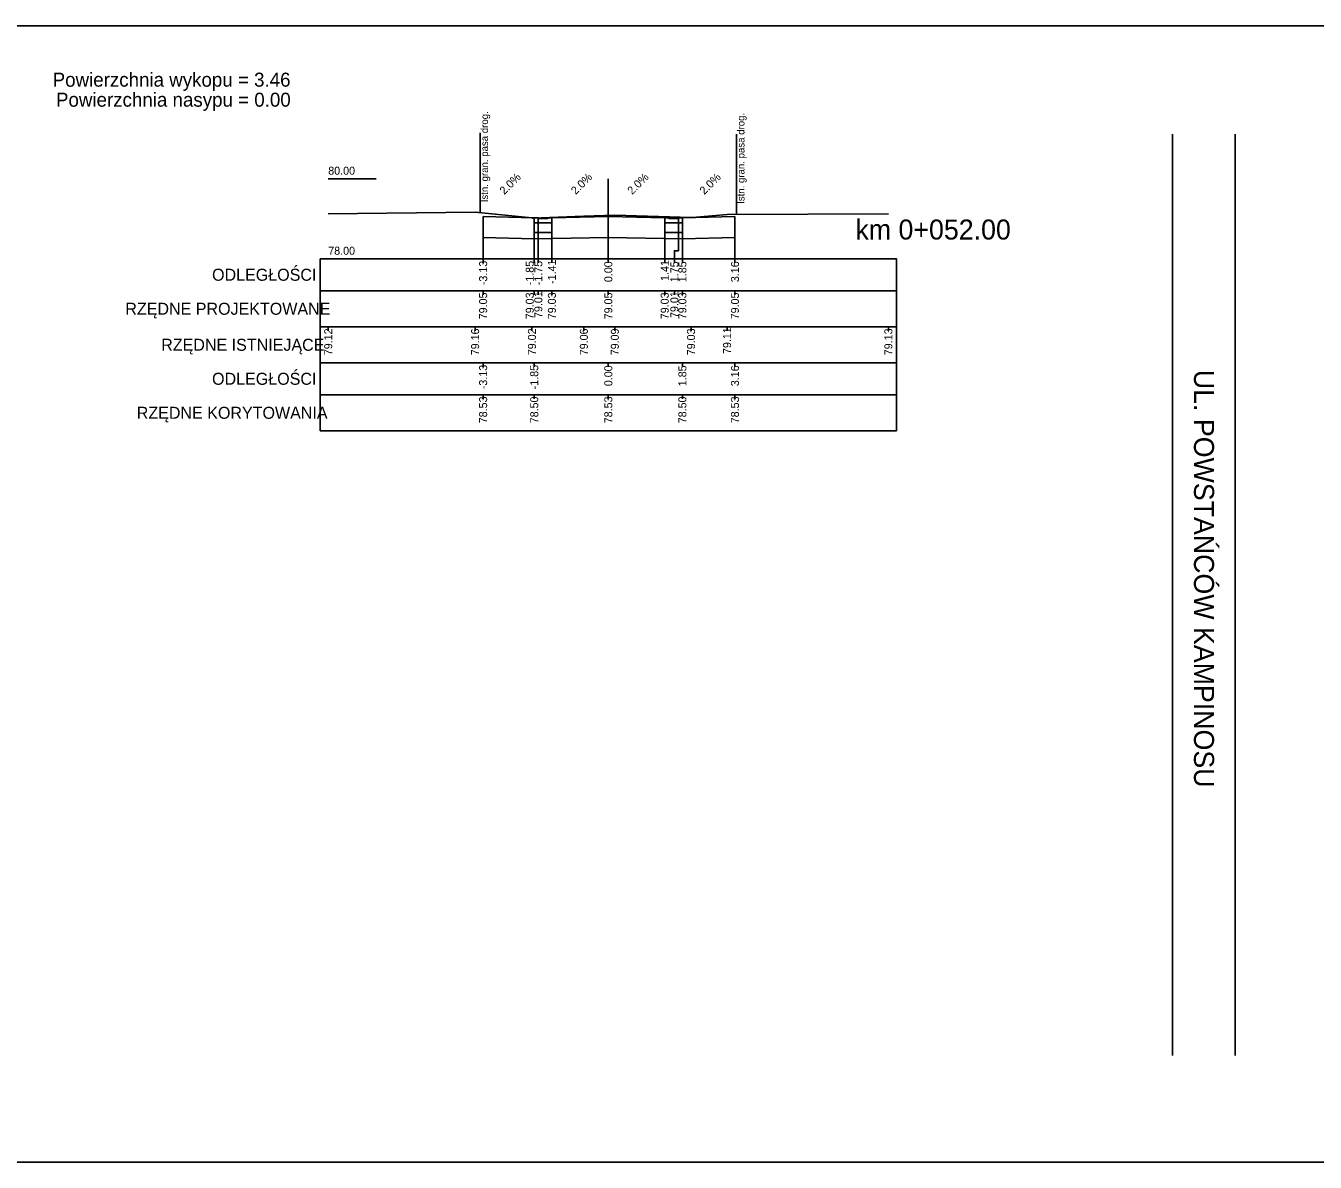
# Model space of a CAD drawing. Extents: x 7492871 to 7493499, y 5802964 to 5802992.
# Drawn here: x 7493073.13 to 7493105.36, y 5802963.88 to 5802992.28 of the extents above; entities that cross this region are included whole.
import ezdxf

# ---------------------------------------------------------------- set-up
doc = ezdxf.new("R2010")
doc.units = 0
for name, color, linetype in [('_wydruk', 7, 'Continuous'), ('d_pop_nasyp_opis', 7, 'Continuous'), ('d_pop_wykop_opis', 7, 'Continuous'), ('opisy_ramki_pop', 7, 'Continuous'), ('pop_comp_kostka', 7, 'Continuous'), ('pop_comp_lawa', 7, 'Continuous'), ('pop_comp_scieralna', 7, 'Continuous'), ('pop_granica_istn', 7, 'Continuous'), ('pop_opis', 7, 'Continuous'), ('pop_os', 7, 'Continuous'), ('pop_pikietaz', 7, 'Continuous'), ('pop_teren', 7, 'Continuous')]:
    doc.layers.add(name, color=color, linetype=linetype)

msp = doc.modelspace()

# ---------------------------------------------------------------- linework, layer by layer
msp.add_lwpolyline([(7493084.563, 5802987.511), (7493085.841, 5802987.485), (7493085.941, 5802987.485), (7493085.942, 5802987.465), (7493086.181, 5802987.465), (7493086.182, 5802987.485), (7493086.282, 5802987.485), (7493087.692, 5802987.513), (7493089.102, 5802987.485), (7493089.202, 5802987.485), (7493089.203, 5802987.465), (7493089.442, 5802987.465), (7493089.443, 5802987.485), (7493089.543, 5802987.485), (7493090.857, 5802987.511)])
at = {"layer": '_wydruk'}
msp.add_lwpolyline([(7492871.369, 5802992.281), (7493499.283, 5802992.281), (7493499.283, 5802963.881), (7492871.369, 5802963.881)], close=True, dxfattribs=at)
at = {"layer": 'opisy_ramki_pop'}
for p, q in [((7493101.797, 5802989.573), (7493101.797, 5802966.547)), ((7493103.363, 5802989.573), (7493103.363, 5802966.547))]:
    msp.add_line(p, q, dxfattribs=at)
for points in [[(7493084.563, 5802986.991), (7493084.563, 5802986.659), (7493084.563, 5802986.659), (7493084.563, 5802986.459)], [(7493085.841, 5802986.956), (7493085.841, 5802986.659), (7493085.841, 5802986.659), (7493085.841, 5802986.459)], [(7493087.692, 5802986.993), (7493087.692, 5802986.659), (7493087.692, 5802986.659), (7493087.692, 5802986.459)], [(7493089.543, 5802986.956), (7493089.543, 5802986.659), (7493089.543, 5802986.659), (7493089.543, 5802986.459)], [(7493090.857, 5802986.991), (7493090.857, 5802986.659), (7493090.857, 5802986.659), (7493090.857, 5802986.459)]]:
    msp.add_lwpolyline(points, dxfattribs=at)
at = {"layer": 'pop_comp_kostka'}
for p, q in [((7493085.941, 5802987.485), (7493085.841, 5802987.485)), ((7493085.841, 5802987.485), (7493085.841, 5802987.355)), ((7493085.841, 5802987.355), (7493086.282, 5802987.355)), ((7493085.942, 5802987.465), (7493085.941, 5802987.485)), ((7493086.181, 5802987.465), (7493085.942, 5802987.465)), ((7493086.182, 5802987.485), (7493086.181, 5802987.465)), ((7493086.282, 5802987.485), (7493086.182, 5802987.485)), ((7493086.282, 5802987.355), (7493086.282, 5802987.485)), ((7493089.202, 5802987.485), (7493089.102, 5802987.485)), ((7493089.102, 5802987.485), (7493089.102, 5802987.355)), ((7493089.102, 5802987.355), (7493089.543, 5802987.355)), ((7493089.203, 5802987.465), (7493089.202, 5802987.485)), ((7493089.442, 5802987.465), (7493089.203, 5802987.465)), ((7493089.443, 5802987.485), (7493089.442, 5802987.465)), ((7493089.543, 5802987.485), (7493089.443, 5802987.485)), ((7493089.543, 5802987.355), (7493089.543, 5802987.485))]:
    msp.add_line(p, q, dxfattribs=at)
at = {"layer": 'pop_comp_lawa'}
for p, q in [((7493086.282, 5802987.355), (7493085.841, 5802987.355)), ((7493085.841, 5802987.355), (7493085.841, 5802987.115)), ((7493086.282, 5802987.115), (7493086.282, 5802987.355)), ((7493089.543, 5802987.355), (7493089.102, 5802987.355)), ((7493089.102, 5802987.355), (7493089.102, 5802987.115)), ((7493089.543, 5802987.115), (7493089.543, 5802987.355)), ((7493085.841, 5802987.115), (7493086.282, 5802987.115)), ((7493089.102, 5802987.115), (7493089.543, 5802987.115))]:
    msp.add_line(p, q, dxfattribs=at)
at = {"layer": 'pop_comp_scieralna'}
for p, q in [((7493085.841, 5802987.485), (7493084.563, 5802987.511)), ((7493084.563, 5802987.511), (7493084.563, 5802986.991)), ((7493085.841, 5802987.115), (7493085.841, 5802987.485)), ((7493087.692, 5802987.513), (7493086.282, 5802987.485)), ((7493086.282, 5802987.485), (7493086.282, 5802987.115)), ((7493087.692, 5802986.993), (7493087.692, 5802987.513)), ((7493089.102, 5802987.485), (7493087.692, 5802987.513)), ((7493087.692, 5802987.513), (7493087.692, 5802986.993)), ((7493089.102, 5802987.115), (7493089.102, 5802987.485)), ((7493090.857, 5802987.511), (7493089.543, 5802987.485)), ((7493089.543, 5802987.485), (7493089.543, 5802987.115)), ((7493090.857, 5802986.991), (7493090.857, 5802987.511)), ((7493086.282, 5802987.115), (7493085.841, 5802987.115)), ((7493089.543, 5802987.115), (7493089.102, 5802987.115)), ((7493084.563, 5802986.991), (7493085.841, 5802986.956)), ((7493085.841, 5802986.956), (7493087.692, 5802986.993)), ((7493087.692, 5802986.993), (7493089.543, 5802986.956)), ((7493089.543, 5802986.956), (7493090.857, 5802986.991))]:
    msp.add_line(p, q, dxfattribs=at)
at = {"layer": 'pop_granica_istn'}
for p, q in [((7493084.488, 5802988.109), (7493084.488, 5802989.609)), ((7493090.896, 5802988.069), (7493090.896, 5802989.569)), ((7493084.488, 5802987.609), (7493084.488, 5802988.109)), ((7493090.896, 5802987.569), (7493090.896, 5802988.069))]:
    msp.add_line(p, q, dxfattribs=at)
at = {"layer": 'pop_opis'}
for p, q in [((7493080.692, 5802988.459), (7493081.892, 5802988.459)), ((7493080.492, 5802986.459), (7493080.492, 5802984.759)), ((7493080.492, 5802986.459), (7493080.492, 5802984.759)), ((7493080.492, 5802986.459), (7493080.492, 5802984.759)), ((7493080.492, 5802986.459), (7493080.492, 5802984.759)), ((7493080.692, 5802986.459), (7493081.892, 5802986.459)), ((7493084.563, 5802986.359), (7493084.563, 5802986.459)), ((7493085.841, 5802986.359), (7493085.841, 5802986.459)), ((7493085.942, 5802986.359), (7493085.942, 5802986.459)), ((7493086.282, 5802986.359), (7493086.282, 5802986.459)), ((7493087.692, 5802986.359), (7493087.692, 5802986.459)), ((7493089.102, 5802986.359), (7493089.102, 5802986.459)), ((7493089.343, 5802986.359), (7493089.343, 5802986.459)), ((7493089.543, 5802986.359), (7493089.543, 5802986.459)), ((7493090.857, 5802986.359), (7493090.857, 5802986.459)), ((7493080.492, 5802985.659), (7493094.892, 5802985.659)), ((7493080.492, 5802985.659), (7493094.892, 5802985.659)), ((7493080.492, 5802985.659), (7493094.892, 5802985.659)), ((7493080.492, 5802985.659), (7493094.892, 5802985.659)), ((7493084.563, 5802985.559), (7493084.563, 5802985.659)), ((7493085.841, 5802985.559), (7493085.841, 5802985.659)), ((7493085.942, 5802985.559), (7493085.942, 5802985.659)), ((7493086.282, 5802985.559), (7493086.282, 5802985.659)), ((7493087.692, 5802985.559), (7493087.692, 5802985.659)), ((7493089.102, 5802985.559), (7493089.102, 5802985.659)), ((7493089.343, 5802985.559), (7493089.343, 5802985.659)), ((7493089.543, 5802985.559), (7493089.543, 5802985.659)), ((7493090.857, 5802985.559), (7493090.857, 5802985.659)), ((7493080.492, 5802984.759), (7493080.492, 5802983.859)), ((7493080.692, 5802984.659), (7493080.692, 5802984.759)), ((7493084.363, 5802984.659), (7493084.363, 5802984.759)), ((7493085.783, 5802984.659), (7493085.783, 5802984.759)), ((7493087.081, 5802984.659), (7493087.081, 5802984.759)), ((7493087.854, 5802984.659), (7493087.854, 5802984.759)), ((7493089.76, 5802984.659), (7493089.76, 5802984.759)), ((7493090.66, 5802984.659), (7493090.66, 5802984.759)), ((7493094.692, 5802984.659), (7493094.692, 5802984.759)), ((7493080.492, 5802983.859), (7493080.492, 5802982.159)), ((7493084.563, 5802983.759), (7493084.563, 5802983.859)), ((7493085.841, 5802983.759), (7493085.841, 5802983.859)), ((7493087.692, 5802983.759), (7493087.692, 5802983.859)), ((7493089.543, 5802983.759), (7493089.543, 5802983.859)), ((7493090.857, 5802983.759), (7493090.857, 5802983.859)), ((7493080.492, 5802983.059), (7493094.892, 5802983.059)), ((7493084.563, 5802982.959), (7493084.563, 5802983.059)), ((7493085.841, 5802982.959), (7493085.841, 5802983.059)), ((7493087.692, 5802982.959), (7493087.692, 5802983.059)), ((7493089.543, 5802982.959), (7493089.543, 5802983.059)), ((7493090.857, 5802982.959), (7493090.857, 5802983.059))]:
    msp.add_line(p, q, dxfattribs=at)
for points in [[(7493084.563, 5802987.511), (7493084.563, 5802986.659), (7493084.563, 5802986.659), (7493084.563, 5802986.459)], [(7493085.841, 5802987.485), (7493085.841, 5802986.659), (7493085.841, 5802986.659), (7493085.841, 5802986.459)], [(7493085.942, 5802987.465), (7493085.942, 5802986.659), (7493085.942, 5802986.659), (7493085.942, 5802986.459)], [(7493086.282, 5802987.485), (7493086.282, 5802986.659), (7493086.282, 5802986.659), (7493086.282, 5802986.459)], [(7493087.692, 5802987.513), (7493087.692, 5802986.659), (7493087.692, 5802986.659), (7493087.692, 5802986.459)], [(7493089.102, 5802987.485), (7493089.102, 5802986.659), (7493089.102, 5802986.659), (7493089.102, 5802986.459)], [(7493089.442, 5802987.465), (7493089.442, 5802986.659), (7493089.343, 5802986.659), (7493089.343, 5802986.459)], [(7493089.543, 5802987.485), (7493089.543, 5802986.659), (7493089.543, 5802986.659), (7493089.543, 5802986.459)], [(7493090.857, 5802987.511), (7493090.857, 5802986.659), (7493090.857, 5802986.659), (7493090.857, 5802986.459)]]:
    msp.add_lwpolyline(points, dxfattribs=at)
for points in [[(7493080.492, 5802986.459), (7493080.492, 5802984.759), (7493094.892, 5802984.759), (7493094.892, 5802986.459)], [(7493080.492, 5802986.459), (7493080.492, 5802984.759), (7493094.892, 5802984.759), (7493094.892, 5802986.459)], [(7493080.492, 5802986.459), (7493080.492, 5802984.759), (7493094.892, 5802984.759), (7493094.892, 5802986.459)], [(7493080.492, 5802986.459), (7493080.492, 5802984.759), (7493094.892, 5802984.759), (7493094.892, 5802986.459)], [(7493080.492, 5802984.759), (7493080.492, 5802983.859), (7493094.892, 5802983.859), (7493094.892, 5802984.759)], [(7493080.492, 5802983.859), (7493080.492, 5802982.159), (7493094.892, 5802982.159), (7493094.892, 5802983.859)]]:
    msp.add_lwpolyline(points, close=True, dxfattribs=at)
at = {"layer": 'pop_os'}
msp.add_line((7493087.692, 5802988.459), (7493087.692, 5802986.459), dxfattribs=at)
at = {"layer": 'pop_teren'}
msp.add_lwpolyline([(7493080.692, 5802987.581), (7493084.363, 5802987.623), (7493085.783, 5802987.479), (7493085.795, 5802987.477), (7493087.081, 5802987.523), (7493087.854, 5802987.549), (7493089.76, 5802987.49), (7493089.784, 5802987.49), (7493089.807, 5802987.493), (7493090.66, 5802987.568), (7493094.692, 5802987.584)], dxfattribs=at)

# ---------------------------------------------------------------- texts
at = {"layer": 'd_pop_nasyp_opis'}
msp.add_text('Powierzchnia nasypu = 0.00', height=0.35, dxfattribs=at).set_placement((7493073.887, 5802990.259))
at = {"layer": 'd_pop_wykop_opis'}
msp.add_text('Powierzchnia wykopu = 3.46', height=0.35, dxfattribs=at).set_placement((7493073.804, 5802990.759))
at = {"layer": 'pop_granica_istn'}
for p in [(7493084.686, 5802987.87), (7493091.095, 5802987.83)]:
    msp.add_text('Istn. gran. pasa drog.', height=0.18, rotation=90, dxfattribs=at).set_placement(p)
at = {"layer": 'pop_opis'}
for s, height, p in [('80.00', 0.2, (7493080.692, 5802988.559)), ('78.00', 0.2, (7493080.692, 5802986.559)), ('ODLEGŁOŚCI', 0.3, (7493077.788, 5802985.909)), ('ODLEGŁOŚCI', 0.3, (7493077.788, 5802985.909)), ('ODLEGŁOŚCI', 0.3, (7493077.788, 5802985.909)), ('ODLEGŁOŚCI', 0.3, (7493077.788, 5802985.909)), ('RZĘDNE PROJEKTOWANE', 0.3, (7493075.62, 5802985.059)), ('RZĘDNE PROJEKTOWANE', 0.3, (7493075.62, 5802985.059)), ('RZĘDNE PROJEKTOWANE', 0.3, (7493075.62, 5802985.059)), ('RZĘDNE PROJEKTOWANE', 0.3, (7493075.62, 5802985.059)), ('RZĘDNE ISTNIEJĄCE', 0.3, (7493076.517, 5802984.159)), ('ODLEGŁOŚCI', 0.3, (7493077.788, 5802983.309)), ('RZĘDNE KORYTOWANIA', 0.3, (7493075.906, 5802982.459))]:
    msp.add_text(s, height=height, dxfattribs=at).set_placement(p)
for s, rotation, p in [('2.0%', 45, (7493085.093, 5802988.048)), ('2.0%', 45, (7493086.878, 5802988.049)), ('2.0%', 45, (7493088.288, 5802988.049)), ('2.0%', 45, (7493090.091, 5802988.048)), ('-3.13', 90, (7493084.663, 5802985.798)), ('-1.85', 90, (7493085.828, 5802985.796)), ('-1.75', 90, (7493086.042, 5802985.796)), ('-1.41', 90, (7493086.382, 5802985.829)), ('0.00', 90, (7493087.792, 5802985.874)), ('1.41', 90, (7493089.202, 5802985.905)), ('1.75', 90, (7493089.443, 5802985.873)), ('1.85', 90, (7493089.643, 5802985.873)), ('3.16', 90, (7493090.957, 5802985.874)), ('79.05', 90, (7493084.663, 5802984.945)), ('79.03', 90, (7493085.828, 5802984.947)), ('79.01', 90, (7493086.042, 5802984.978)), ('79.03', 90, (7493086.382, 5802984.947)), ('79.05', 90, (7493087.792, 5802984.945)), ('79.03', 90, (7493089.202, 5802984.947)), ('79.01', 90, (7493089.443, 5802984.978)), ('79.03', 90, (7493089.643, 5802984.947)), ('79.05', 90, (7493090.957, 5802984.945)), ('79.12', 90, (7493080.792, 5802984.048)), ('79.16', 90, (7493084.463, 5802984.047)), ('79.02', 90, (7493085.883, 5802984.048)), ('79.06', 90, (7493087.181, 5802984.047)), ('79.09', 90, (7493087.954, 5802984.046)), ('79.03', 90, (7493089.86, 5802984.047)), ('79.11', 90, (7493090.76, 5802984.078)), ('79.13', 90, (7493094.792, 5802984.047)), ('-3.13', 90, (7493084.663, 5802983.198)), ('-1.85', 90, (7493085.941, 5802983.196)), ('0.00', 90, (7493087.792, 5802983.274)), ('1.85', 90, (7493089.643, 5802983.273)), ('3.16', 90, (7493090.957, 5802983.274)), ('78.53', 90, (7493084.663, 5802982.347)), ('78.50', 90, (7493085.941, 5802982.347)), ('78.53', 90, (7493087.792, 5802982.347)), ('78.50', 90, (7493089.643, 5802982.347)), ('78.53', 90, (7493090.957, 5802982.347))]:
    msp.add_text(s, height=0.2, rotation=rotation, dxfattribs=at).set_placement(p)
at = {"layer": 'pop_pikietaz'}
msp.add_text('km 0+052.00', height=0.5, dxfattribs=at).set_placement((7493093.868, 5802986.939))
msp.add_text('UL. POWSTAŃCÓW KAMPINOSU', height=0.5, rotation=270, dxfattribs=at).set_placement((7493102.331, 5802983.683))

doc.saveas('drawing.dxf')
